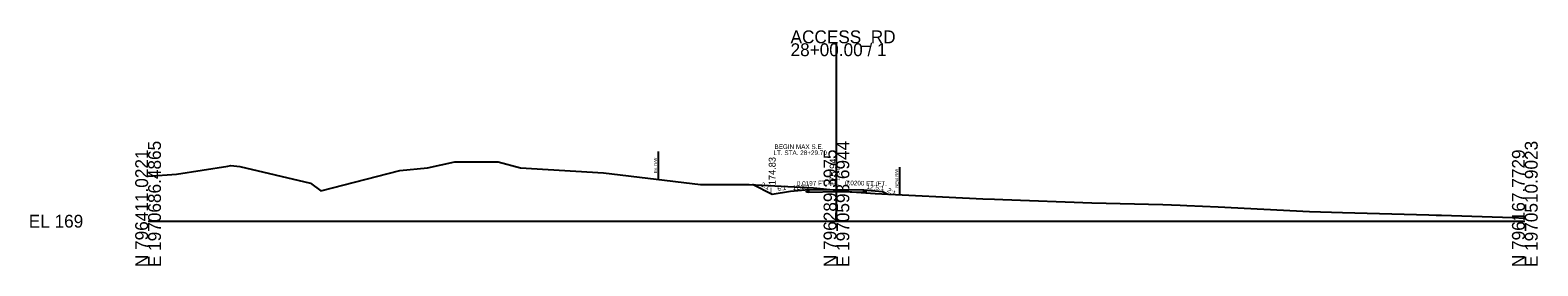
# Model space of a CAD drawing. Extents: x 27306 to 1891059, y 5381 to 776288.
# Drawn here: x 28306 to 28634.5, y 9380.7 to 9432 of the extents above; entities that cross this region are included whole.
import ezdxf

# ---------------------------------------------------------------- set-up
doc = ezdxf.new("R2010")
doc.units = 0
for name, color, linetype in [('RD_EX_BldgApp', 7, 'Continuous'), ('RD_EX_H2O_BlueLn', 7, 'Continuous'), ('RD_EX_RailRoad', 7, 'Continuous'), ('RD_HC_Cl', 7, 'Continuous'), ('RD_HC_CL_Rel', 7, 'Continuous'), ('RD_HC_Data', 7, 'Continuous'), ('RD_HC_Data_Tic', 7, 'Continuous'), ('RD_HC_TX_Sta50', 7, 'Continuous'), ('RD_PD_ALT2_CL', 7, 'Continuous'), ('RD_PD_ALT3_CL', 7, 'Continuous'), ('RD_PD_ALT5_CL', 7, 'Continuous'), ('RD_PD_Final_Cl', 7, 'Continuous'), ('RD_PD_Final_TrvlWay', 7, 'Continuous'), ('RD_PD_MedBWall', 7, 'Continuous'), ('RD_TX_RoadID', 7, 'Continuous')]:
    doc.layers.add(name, color=color, linetype=linetype)

msp = doc.modelspace()

# ---------------------------------------------------------------- linework, layer by layer
at = {"layer": 'RD_EX_H2O_BlueLn'}
for p, q in [((28475.65, 9397.25), (28471.65, 9396.93)), ((28487.65, 9397.25), (28491.65, 9396.93))]:
    msp.add_line(p, q, dxfattribs=at)
at = {"layer": 'RD_EX_RailRoad'}
for p, q in [((28475.15, 9396.99), (28475.65, 9397)), ((28475.15, 9396.74), (28475.15, 9396.99)), ((28475.65, 9396.75), (28475.15, 9396.74)), ((28475.65, 9397), (28475.65, 9397.25)), ((28475.65, 9396.75), (28481.65, 9396.87)), ((28481.65, 9396.87), (28487.65, 9396.75)), ((28487.65, 9397), (28487.65, 9397.25)), ((28488.15, 9396.99), (28487.65, 9397)), ((28487.65, 9396.75), (28488.15, 9396.74)), ((28488.15, 9396.74), (28488.15, 9396.99))]:
    msp.add_line(p, q, dxfattribs=at)
at = {"layer": 'RD_HC_Cl'}
for p, q in [((28481.65, 9390.44), (28481.65, 9429.14)), ((28331.65, 9390.44), (28481.65, 9390.44)), ((28481.65, 9390.44), (28631.65, 9390.44))]:
    msp.add_line(p, q, dxfattribs=at)
at = {"layer": 'RD_PD_ALT5_CL'}
for p, q in [((28467.65, 9396.26), (28463.35, 9398.41)), ((28471.65, 9396.93), (28467.65, 9396.26)), ((28491.65, 9396.93), (28492.87, 9396.32))]:
    msp.add_line(p, q, dxfattribs=at)
at = {"layer": 'RD_PD_Final_Cl'}
msp.add_lwpolyline([(28331.65, 9400.26), (28337.83, 9400.69), (28349.06, 9402.38), (28349.7, 9402.54), (28351.65, 9402.36), (28367.02, 9398.69), (28369.31, 9397.02), (28386.53, 9401.45), (28392.56, 9402.02), (28398.5, 9403.32), (28407.94, 9403.34), (28412.82, 9402.05), (28430.91, 9400.95), (28452.04, 9398.44), (28462.65, 9398.45), (28476.67, 9397.73), (28481.65, 9397.21), (28484.97, 9396.86), (28490.06, 9396.46), (28513.58, 9395.31), (28516.09, 9395.24), (28517.9, 9395.18), (28537.27, 9394.45), (28552.75, 9394.11), (28556.53, 9393.94), (28557.98, 9393.88), (28564.84, 9393.56), (28584.74, 9392.54), (28591.9, 9392.36), (28610.76, 9391.82), (28612.35, 9391.75), (28613.49, 9391.72), (28628.97, 9391.25), (28631.65, 9391.12)], dxfattribs=at)
at = {"layer": 'RD_PD_Final_TrvlWay'}
msp.add_line((28442.81, 9405.58), (28442.81, 9399.58), dxfattribs=at)
at = {"layer": 'RD_PD_MedBWall'}
for p, q in [((28475.65, 9397.25), (28481.65, 9397.37)), ((28481.65, 9397.37), (28487.65, 9397.25))]:
    msp.add_line(p, q, dxfattribs=at)
at = {"layer": 'RD_TX_RoadID'}
msp.add_line((28495.37, 9402.2), (28495.37, 9396.2), dxfattribs=at)

# ---------------------------------------------------------------- texts
at = {"layer": 'RD_EX_BldgApp'}
msp.add_text('175.77', height=0.8, rotation=90, dxfattribs=at).set_placement((28482.35, 9399.24))
at = {"layer": 'RD_HC_Cl'}
for s, p in [('ACCESS_RD', (28471.65, 9429.14)), ('28+00.00 / 1', (28471.65, 9426.34)), ('EL 169', (28305.65, 9389.04))]:
    msp.add_text(s, height=2.8, dxfattribs=at).set_placement(p)
for s, p in [('E 1970686.4865', (28334.45, 9380.44)), ('E 1970598.6944', (28484.45, 9380.44)), ('E 1970510.9023', (28634.45, 9380.44)), ('N 796411.0221', (28331.65, 9380.44)), ('N 796289.3975', (28481.65, 9380.44)), ('N 796167.7729', (28631.65, 9380.44))]:
    msp.add_text(s, height=2.8, rotation=90, dxfattribs=at).set_placement(p)
at = {"layer": 'RD_HC_CL_Rel'}
for s, p in [('BEGIN MAX S.E.', (28468.14, 9406.15)), ('LT. STA. 28+29.70', (28467.92, 9404.83))]:
    msp.add_text(s, height=1, dxfattribs=at).set_placement(p)
at = {"layer": 'RD_HC_Data'}
msp.add_text(' 175.94', height=1.5, rotation=90, dxfattribs=at).set_placement((28481.65, 9397.37))
at = {"layer": 'RD_HC_Data_Tic'}
for rotation, p in [(4.5739, (28472.15, 9397.22)), (355.4261, (28488.19, 9397.46))]:
    msp.add_text('12.5:1', height=1, rotation=rotation, dxfattribs=at).set_placement(p)
at = {"layer": 'RD_HC_TX_Sta50'}
for s, rotation, p in [('0.0197 FT./FT.', 1.1458, (28473.04, 9398.13)), ('2:1', 333.4349, (28465.09, 9398.1)), ('6:1', 9.4623, (28468.87, 9396.97)), ('0.0200 FT./FT.', 358.8542, (28483.51, 9398.29)), ('2:1', 331.3922, (28492.59, 9396.91))]:
    msp.add_text(s, height=1, rotation=rotation, dxfattribs=at).set_placement(p)
at = {"layer": 'RD_PD_ALT2_CL'}
msp.add_text('174.83', height=1.5, rotation=90, dxfattribs=at).set_placement((28468.4, 9398.26))
at = {"layer": 'RD_PD_ALT3_CL'}
msp.add_text('L', height=1.5, dxfattribs=at).set_placement((28467.14, 9396.26))
msp.add_text('L', height=1.5, dxfattribs=at).set_placement((28467.14, 9396.26))
at = {"layer": 'RD_PD_Final_TrvlWay'}
msp.add_text('Ex. R/W ', height=0.65, rotation=90, dxfattribs=at).set_placement((28442.56, 9400.96))
at = {"layer": 'RD_TX_RoadID'}
msp.add_text('NEW R/W ', height=0.65, rotation=90, dxfattribs=at).set_placement((28495.1, 9397.76))

doc.saveas('drawing.dxf')
